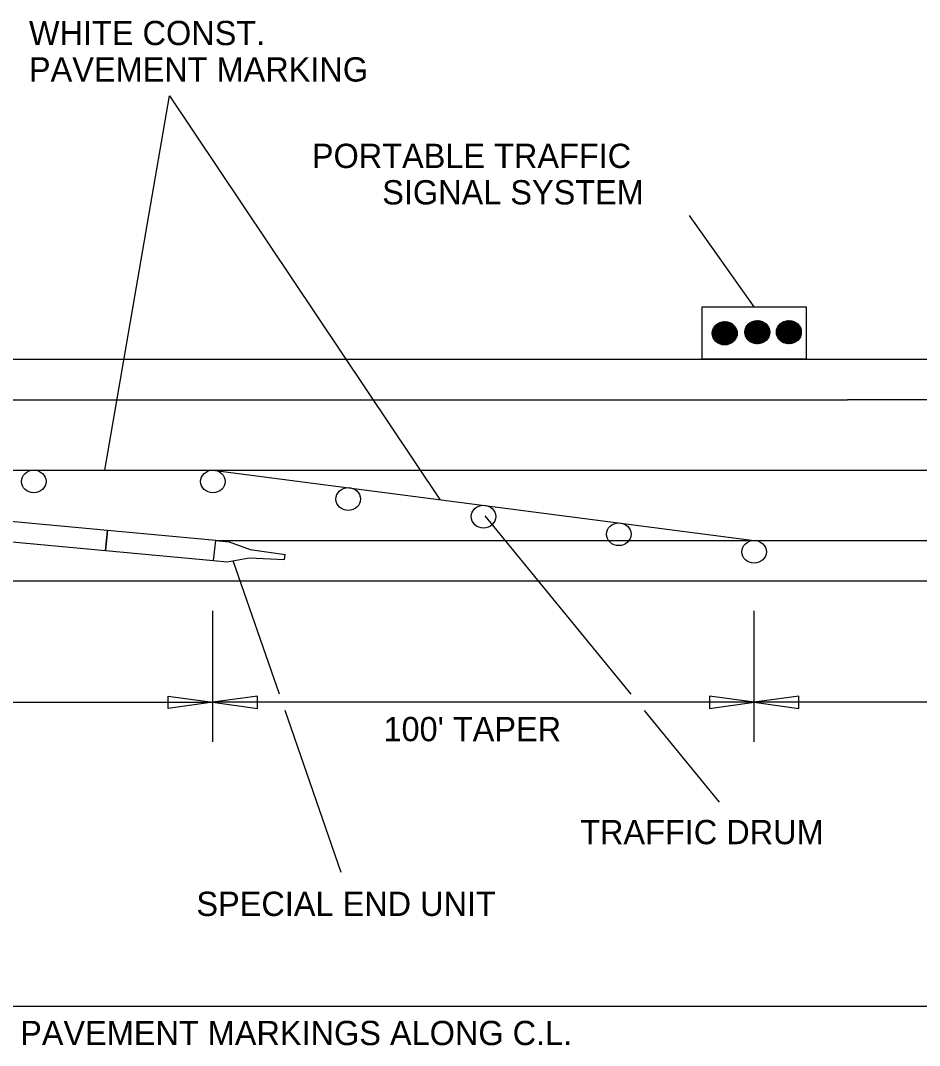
# Model space of a CAD drawing. Extents: x 1807779 to 1818251, y 673292 to 678849.
# Drawn here: x 1811213.3 to 1811429.4, y 676570 to 676816.3 of the extents above; entities that cross this region are included whole.
import ezdxf

# ---------------------------------------------------------------- set-up
doc = ezdxf.new("R2010")
doc.units = 0
doc.layers.add('Default', color=7, linetype='Continuous')
doc.layers.add('T_Vehicle Path Rt', color=7, linetype='Continuous')

msp = doc.modelspace()

# ---------------------------------------------------------------- linework, layer by layer
at = {"layer": 'Default'}
for p, q in [((1811389.63, 676747.55), (1811374.14, 676769.45)), ((1811393.29, 676740.7), (1811389.62, 676744.12)), ((1811393.33, 676740.84), (1811389.77, 676744.16)), ((1811393.36, 676740.98), (1811389.92, 676744.18)), ((1811393.38, 676741.13), (1811390.09, 676744.2)), ((1811393.39, 676741.29), (1811390.26, 676744.21)), ((1811393.39, 676741.46), (1811390.44, 676744.22)), ((1811393.39, 676741.64), (1811390.63, 676744.21)), ((1811393.36, 676741.84), (1811390.84, 676744.19)), ((1811393.32, 676742.05), (1811391.07, 676744.15)), ((1811400.9, 676740.76), (1811397.27, 676744.14)), ((1811400.93, 676740.9), (1811397.42, 676744.17)), ((1811400.96, 676741.05), (1811397.58, 676744.19)), ((1811400.97, 676741.2), (1811397.75, 676744.21)), ((1811400.98, 676741.37), (1811397.92, 676744.22)), ((1811400.98, 676741.54), (1811398.11, 676744.21)), ((1811400.96, 676741.73), (1811398.31, 676744.2)), ((1811400.93, 676741.93), (1811398.53, 676744.17)), ((1811400.88, 676742.15), (1811398.77, 676744.12)), ((1811383.21, 676738.43), (1811379.65, 676741.75)), ((1811383.36, 676738.46), (1811379.68, 676741.89)), ((1811383.5, 676738.5), (1811379.73, 676742.02)), ((1811383.64, 676738.55), (1811379.77, 676742.15)), ((1811383.77, 676738.6), (1811379.83, 676742.27)), ((1811383.9, 676738.65), (1811379.88, 676742.39)), ((1811384.02, 676738.71), (1811379.95, 676742.5)), ((1811384.14, 676738.77), (1811380.01, 676742.61)), ((1811384.25, 676738.84), (1811380.09, 676742.72)), ((1811384.36, 676738.91), (1811380.16, 676742.82)), ((1811384.46, 676738.99), (1811380.24, 676742.92)), ((1811384.56, 676739.06), (1811380.33, 676743.01)), ((1811384.66, 676739.15), (1811380.41, 676743.1)), ((1811384.75, 676739.23), (1811380.51, 676743.18)), ((1811384.84, 676739.32), (1811380.6, 676743.27)), ((1811384.92, 676739.42), (1811380.7, 676743.35)), ((1811385, 676739.51), (1811380.81, 676743.42)), ((1811385.08, 676739.61), (1811380.92, 676743.49)), ((1811385.15, 676739.72), (1811381.03, 676743.56)), ((1811385.22, 676739.83), (1811381.15, 676743.62)), ((1811385.28, 676739.94), (1811381.27, 676743.68)), ((1811385.34, 676740.06), (1811381.4, 676743.73)), ((1811385.39, 676740.18), (1811381.53, 676743.78)), ((1811385.44, 676740.31), (1811381.66, 676743.83)), ((1811385.48, 676740.44), (1811381.81, 676743.87)), ((1811385.52, 676740.58), (1811381.95, 676743.9)), ((1811385.55, 676740.73), (1811382.11, 676743.93)), ((1811385.57, 676740.88), (1811382.27, 676743.95)), ((1811385.58, 676741.04), (1811382.45, 676743.96)), ((1811385.58, 676741.21), (1811382.63, 676743.96)), ((1811385.57, 676741.39), (1811382.82, 676743.95)), ((1811385.55, 676741.58), (1811383.03, 676743.93)), ((1811385.51, 676741.79), (1811383.26, 676743.89)), ((1811385.43, 676742.03), (1811383.51, 676743.82)), ((1811385.32, 676742.31), (1811383.81, 676743.71)), ((1811385.1, 676742.69), (1811384.22, 676743.51)), ((1811390.7, 676738.64), (1811387.41, 676741.71)), ((1811390.87, 676738.66), (1811387.43, 676741.86)), ((1811391.02, 676738.69), (1811387.46, 676742.01)), ((1811391.17, 676738.72), (1811387.5, 676742.15)), ((1811391.31, 676738.76), (1811387.54, 676742.28)), ((1811391.45, 676738.8), (1811387.59, 676742.41)), ((1811391.58, 676738.85), (1811387.64, 676742.53)), ((1811391.71, 676738.91), (1811387.7, 676742.65)), ((1811391.83, 676738.97), (1811387.76, 676742.76)), ((1811391.95, 676739.03), (1811387.83, 676742.87)), ((1811392.06, 676739.1), (1811387.9, 676742.97)), ((1811392.17, 676739.17), (1811387.97, 676743.07)), ((1811392.27, 676739.24), (1811388.05, 676743.17)), ((1811392.37, 676739.32), (1811388.14, 676743.27)), ((1811392.47, 676739.4), (1811388.23, 676743.35)), ((1811392.56, 676739.49), (1811388.32, 676743.44)), ((1811392.65, 676739.58), (1811388.42, 676743.52)), ((1811392.73, 676739.67), (1811388.52, 676743.6)), ((1811392.81, 676739.77), (1811388.62, 676743.68)), ((1811392.89, 676739.87), (1811388.73, 676743.75)), ((1811392.96, 676739.97), (1811388.84, 676743.81)), ((1811393.03, 676740.08), (1811388.96, 676743.88)), ((1811393.09, 676740.2), (1811389.08, 676743.93)), ((1811393.15, 676740.32), (1811389.21, 676743.99)), ((1811393.2, 676740.44), (1811389.34, 676744.04)), ((1811393.25, 676740.57), (1811389.48, 676744.08)), ((1811393.25, 676742.29), (1811391.32, 676744.08)), ((1811393.13, 676742.57), (1811391.63, 676743.97)), ((1811392.91, 676742.95), (1811392.03, 676743.76)), ((1811398.36, 676738.65), (1811395.01, 676741.78)), ((1811398.52, 676738.67), (1811395.03, 676741.93)), ((1811398.68, 676738.7), (1811395.06, 676742.07)), ((1811398.82, 676738.74), (1811395.1, 676742.2)), ((1811398.96, 676738.78), (1811395.15, 676742.33)), ((1811399.1, 676738.83), (1811395.2, 676742.46)), ((1811399.23, 676738.88), (1811395.25, 676742.58)), ((1811399.35, 676738.93), (1811395.31, 676742.7)), ((1811399.47, 676738.99), (1811395.38, 676742.81)), ((1811399.59, 676739.06), (1811395.45, 676742.92)), ((1811399.7, 676739.13), (1811395.52, 676743.02)), ((1811399.8, 676739.2), (1811395.6, 676743.12)), ((1811399.91, 676739.28), (1811395.68, 676743.21)), ((1811400, 676739.36), (1811395.77, 676743.31)), ((1811400.1, 676739.44), (1811395.86, 676743.39)), ((1811400.19, 676739.53), (1811395.95, 676743.48)), ((1811400.28, 676739.62), (1811396.05, 676743.56)), ((1811400.36, 676739.71), (1811396.15, 676743.63)), ((1811400.44, 676739.81), (1811396.26, 676743.71)), ((1811400.51, 676739.92), (1811396.37, 676743.78)), ((1811400.58, 676740.02), (1811396.48, 676743.84)), ((1811400.65, 676740.13), (1811396.6, 676743.9)), ((1811400.71, 676740.25), (1811396.72, 676743.96)), ((1811400.81, 676740.49), (1811396.99, 676744.06)), ((1811400.86, 676740.62), (1811397.13, 676744.1)), ((1811400.79, 676742.41), (1811399.04, 676744.04)), ((1811400.64, 676742.72), (1811399.37, 676743.9)), ((1811400.24, 676743.26), (1811399.96, 676743.53)), ((1811382.72, 676738.37), (1811379.58, 676741.29)), ((1811382.54, 676738.37), (1811379.58, 676741.12)), ((1811382.34, 676738.38), (1811379.59, 676740.94)), ((1811382.89, 676738.38), (1811379.6, 676741.45)), ((1811382.14, 676738.4), (1811379.61, 676740.75)), ((1811383.05, 676738.4), (1811379.62, 676741.61)), ((1811381.91, 676738.44), (1811379.66, 676740.54)), ((1811381.65, 676738.51), (1811379.73, 676740.3)), ((1811381.35, 676738.61), (1811379.84, 676740.02)), ((1811380.95, 676738.82), (1811380.07, 676739.64)), ((1811390.35, 676738.63), (1811387.39, 676741.38)), ((1811390.53, 676738.63), (1811387.4, 676741.55)), ((1811390.16, 676738.63), (1811387.4, 676741.2)), ((1811389.95, 676738.66), (1811387.43, 676741.01)), ((1811389.72, 676738.7), (1811387.47, 676740.79)), ((1811389.47, 676738.76), (1811387.54, 676740.56)), ((1811389.17, 676738.87), (1811387.66, 676740.28)), ((1811388.76, 676739.08), (1811387.88, 676739.9)), ((1811398.02, 676738.63), (1811394.98, 676741.46)), ((1811398.2, 676738.63), (1811394.99, 676741.62)), ((1811397.83, 676738.63), (1811394.99, 676741.28)), ((1811397.63, 676738.64), (1811395, 676741.09)), ((1811397.41, 676738.68), (1811395.04, 676740.89)), ((1811397.17, 676738.73), (1811395.09, 676740.67)), ((1811396.89, 676738.82), (1811395.19, 676740.41)), ((1811396.55, 676738.96), (1811395.35, 676740.09)), ((1811130.01, 676734.92), (1812078.25, 676734.92)), ((1811130.01, 676725.19), (1811412.11, 676725.19)), ((1811581.37, 676725.19), (1811412.11, 676725.19)), ((1810973.46, 676708.29), (1811517.44, 676708.29)), ((1811259.55, 676708.29), (1811389.63, 676691.38)), ((1811324.92, 676697.28), (1811360, 676654.43)), ((1811260.16, 676691.38), (1811516.75, 676691.38)), ((1811275.56, 676654.43), (1811264.43, 676686.49)), ((1811130.01, 676681.65), (1812078.25, 676681.65)), ((1811259.55, 676642.96), (1811259.55, 676674.42)), ((1811389.63, 676642.96), (1811389.63, 676674.42)), ((1811248.8, 676650.98), (1811248.8, 676653.98)), ((1811248.8, 676653.98), (1811259.55, 676652.48)), ((1811270.3, 676653.98), (1811259.55, 676652.48)), ((1811270.3, 676650.98), (1811270.3, 676653.98)), ((1811389.63, 676652.48), (1811378.88, 676653.98)), ((1811378.88, 676653.98), (1811378.88, 676650.98)), ((1811400.39, 676653.98), (1811389.63, 676652.48)), ((1811400.39, 676650.98), (1811400.39, 676653.98)), ((1811103.4, 676652.48), (1811259.55, 676652.48)), ((1811259.55, 676652.48), (1811248.8, 676650.98)), ((1811259.55, 676652.48), (1811270.3, 676650.98)), ((1811389.63, 676652.48), (1811259.55, 676652.48)), ((1811290.42, 676611.61), (1811276.91, 676650.54)), ((1811363.19, 676650.54), (1811381.23, 676628.49)), ((1811378.88, 676650.98), (1811389.63, 676652.48)), ((1811389.63, 676652.48), (1811400.39, 676650.98)), ((1811519.69, 676652.48), (1811389.63, 676652.48)), ((1810973.46, 676579.43), (1811519.69, 676579.43))]:
    msp.add_line(p, q, dxfattribs=at)
for points in [[(1811233.54, 676708.29), (1811249.1, 676798.2), (1811314.06, 676701.2)], [(1810973.46, 676708.29), (1811259.55, 676708.29)]]:
    msp.add_lwpolyline(points, dxfattribs=at)
msp.add_lwpolyline([(1811377.12, 676734.92), (1811377.12, 676747.55), (1811402.15, 676747.55), (1811402.15, 676734.92)], close=True, dxfattribs=at)
for centre, major_axis in [((1811390.39, 676741.42), (3, 0)), ((1811397.98, 676741.42), (3, 0)), ((1811382.58, 676741.16), (3, 0)), ((1811216.5, 676705.55), (-2.94, 0)), ((1811259.55, 676705.55), (-2.94, 0)), ((1811292.07, 676701.32), (-2.94, 0)), ((1811324.59, 676697.1), (-2.94, 0)), ((1811357.11, 676692.87), (-2.94, 0)), ((1811389.63, 676688.64), (-2.94, 0))]:
    msp.add_ellipse(centre, major_axis=major_axis, ratio=0.93178, dxfattribs=at)
at = {"layer": 'T_Vehicle Path Rt'}
for p, q in [((1811259.71, 676686.53), (1811260.22, 676691.37)), ((1811260.22, 676691.37), (1811263.47, 676691.07)), ((1811263.47, 676691.07), (1811268.51, 676689.16)), ((1811268.51, 676689.16), (1811276.91, 676687.99)), ((1811276.78, 676686.78), (1811276.91, 676687.99)), ((1811259.71, 676686.53), (1811262.95, 676686.23)), ((1811262.95, 676686.23), (1811268.3, 676687.18)), ((1811268.3, 676687.18), (1811276.78, 676686.78))]:
    msp.add_line(p, q, dxfattribs=at)
for points in [[(1811234.26, 676693.78), (1811208.3, 676696.19), (1811207.78, 676691.35), (1811233.74, 676688.94)], [(1811260.22, 676691.37), (1811234.26, 676693.78), (1811233.74, 676688.94), (1811259.71, 676686.53)]]:
    msp.add_lwpolyline(points, close=True, dxfattribs=at)

# ---------------------------------------------------------------- texts
at = {"layer": 'Default'}
for s, p in [('WHITE CONST.', (1811215.34, 676810.4)), ('PAVEMENT MARKING', (1811215.34, 676801.65)), ('PORTABLE TRAFFIC', (1811283.34, 676780.88)), ('SIGNAL SYSTEM', (1811300.25, 676772.12)), ("100' TAPER", (1811300.55, 676643.13)), ('TRAFFIC DRUM', (1811347.82, 676618.38)), ('SPECIAL END UNIT', (1811255.59, 676601.13)), ('REMOVE EXISTING YELLOW PAVEMENT MARKINGS ALONG C.L.', (1811103.97, 676570.09))]:
    msp.add_text(s, height=5.835, dxfattribs=at).set_placement(p)

doc.saveas('drawing.dxf')
